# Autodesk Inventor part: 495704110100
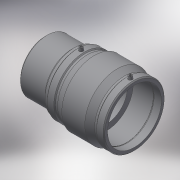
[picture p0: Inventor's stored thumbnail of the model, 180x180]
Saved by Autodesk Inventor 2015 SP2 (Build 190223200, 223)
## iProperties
Created: 2017-06
Part Number: 495704110100
Material: Generic
Description: PLASSON PE CAST IRON SPIGOT COUPLER TRANSITION  110-100
Document SubType Name: Modeling
Designer: KIM
Mass: 55.0731 g
Surface Area: 148.067 cm^2
Volume: 55.0731 cm^3
Density: 1 g/cm^3
Appearance: Default
Author: KIM
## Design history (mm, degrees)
derived "495704.ipt"
feature "Solid1::495704.ipt"
tag "TaggingFeature1"
body "Solid1"
other parameters: "d13" = 163, "d14" = 17.6296, "d17" = 104.5, "d19" = 3.52592, "d20" = 168 deg, "d22" = 126.9, "d23" = 135, "d24" = 123.093, "d25" = 135 deg, "d26" = 65.2, "d27" = 135 deg, "d29" = 79, "d35" = 15, "d39" = 5 deg, "d45" = 4, "d46" = 14, "d47" = 0, "d50" = 3, "d51" = 0, "d52" = 23.2, "d53" = 5.8, "d54" = 118, "d55" = 0.1, "d56" = 129.8, "d57" = 96, "d58" = 112, "d60" = 84, "d62" = 3.54, "d65" = 5.9, "L_" = 275, "D_1" = 135, "A_" = 79, "d_2" = 12, "L_2" = 112, "H_" = 96, "D_" = 118, "d_1" = 84
